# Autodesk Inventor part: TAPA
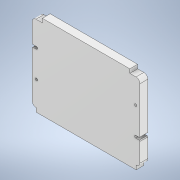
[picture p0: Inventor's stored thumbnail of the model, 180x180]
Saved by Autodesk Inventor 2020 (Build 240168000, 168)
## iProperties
Created: 2022-09
Part Number: TAPA
Material: Tuberías de PVC
Document SubType Name: Modeling
Designer: SEBAS
Density: 1.4 g/cm^3
Appearance: Suave - Blanco
Author: SEBAS
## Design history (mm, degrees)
sketch "Boceto1"
  geometry: L1 (-37, -27)-(37, -27); L2 (37, -27)-(37, 27); L3 (37, 27)-(-37, 27); L4 (-37, 27)-(-37, -27); L5 (-37, -27)-(37, 27); L6 (37, -27)-(-37, 27); L7 (-37, 0)-(0, 0); L8 (0, 0)-(0, 27); L9 (-28, 27)-(-28, 24.5); L10 (-28, 24.5)-(-32, 24.5); L11 (-32, 24.5)-(-32, 22); L12 (-32, 22)-(-34.5, 22); L13 (-34.5, 22)-(-34.5, 10); L14 (-34.5, 10)-(-34, 10); L15 (-34, 10)-(-34, 9.5); L16 (-34, 9.5)-(-31.75, 9.5); L17 (-31.75, 9.5)-(-31.75, 8); L18 (-31.75, 8)-(-34, 8); L19 (-34, 7.5)-(-34.5, 7.5); L20 (-34, 7.5)-(-34, 8); L21 (-34.5, 7.5)-(-34.5, 0); L22 (-28, 27)-(0, 27); L23 (-34.5, 0)-(-34.5, -22); L24 (-32, -22)-(-34.5, -22); L25 (-32, -22)-(-32, -24.5); L26 (-32, -24.5)-(-32, -27); L27 (-32, -27)-(0, -27); L28 (0, 27)-(28, 27); L29 (28, 27)-(28, 24.5); L30 (28, 24.5)-(32, 24.5); L31 (32, 24.5)-(32, 22); L32 (32, 22)-(37, 22); L33 (34.5, 22)-(34.5, 0); L34 (34.5, 0)-(34.5, -7.5); L35 (34, -7.5)-(34.5, -7.5); L36 (34, -7.5)-(34, -8); L37 (34, -8)-(31.75, -8); L38 (31.75, -9.5)-(34, -9.5); L39 (31.75, -8)-(31.75, -9.5); L40 (0, -27)-(32, -27); L41 (32, -22)-(34.5, -22); L42 (32, -22)-(32, -24.5); L43 (32, -24.5)-(32, -27); L44 (34.5, -22)-(34.5, -10); C1 r 0.75 at (-31.75, -8.75); C2 r 0.75 at (31.75, 8.75); A1 r 2.5 centre (-32, 22) between (-32, 24.5) and (-34.5, 22); A2 r 0.5 centre (-34, 10) between (-34.5, 10) and (-34, 9.5); A3 r 0.75 centre (-31.75, 8.75) between (-31.75, 8) and (-31.75, 9.5); A4 r 0.5 centre (-34, 7.5) between (-34, 8) and (-34.5, 7.5); A5 r 2.5 centre (-32, -22) between (-34.5, -22) and (-32, -24.5); A6 r 2.5 centre (32, 22) between (34.5, 22) and (32, 24.5); A7 r 0.5 centre (34, -7.5) between (34, -8) and (34.5, -7.5); A8 r 0.75 centre (31.75, -8.75) between (31.75, -8) and (31.75, -9.5); A9 r 0.5 centre (34, -10) between (34.5, -10) and (34, -9.5); A10 r 2.5 centre (32, -22) between (32, -24.5) and (34.5, -22); 5 further points
  constraints: 88 end point, 21 point on circle, 12 centre point, 11 horizontal, 11 perpendicular, 11 vertical, 11 vertical alignment, 9 equal radius, 9 midpoint, 8 equal length, 7 horizontal alignment, 7 point on line, 7 tangent, 2 parallel, 1 collinear
  dimensions: "d0" = 54 distance between parallel lines of L1 L3; "d1" = 74 distance of L2.end L3.end; "d17" = 2.5 distance of L9.start L9.end; "d18" = 4 distance of L9.end L10.end; "d20" = 2.5 radius of A1; "d21" = 12 distance of L12.end L13.end; "d22" = 2.5 distance between parallel lines of L4 L13; "d23" = 1 diameter of A2; "d24" = 2.25 distance of L15.end L16.end; "d25" = 1.5 diameter of A3; "d26" = 2.5 distance between parallel lines of L2 L33; "d27" = 5 distance of L1.end L40.end; "d28" = 8.75 vertical distance of L21.end A3.centre (derived); "d29" = 17.5 distance of C1.centre A3.centre
extrude "Extrusión1" new body sketch "Boceto1" distance "d15" = 5; taper "d16" = 0 deg
node "Sólido1"
